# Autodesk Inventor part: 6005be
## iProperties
Shininess: 64.0
Length Units: 11269
Angle Units: 11279
Time Units: 11290
Mass Units: 11283
Length Display Precision: 3
Angle Display Precision: 2
Compacted: True
Part Number: 6005be
Document SubType Name: Modeling
Created: 2004-09
Material: Par défaut
Density: 1 g/cm^3
Density: 0.0
Volumn: 0.0
Area: 0.0
PropertySet Name: Model Information
Control State: 0
Master: False
Checked Out: False
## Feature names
1. Révolution1 [Revolution]
